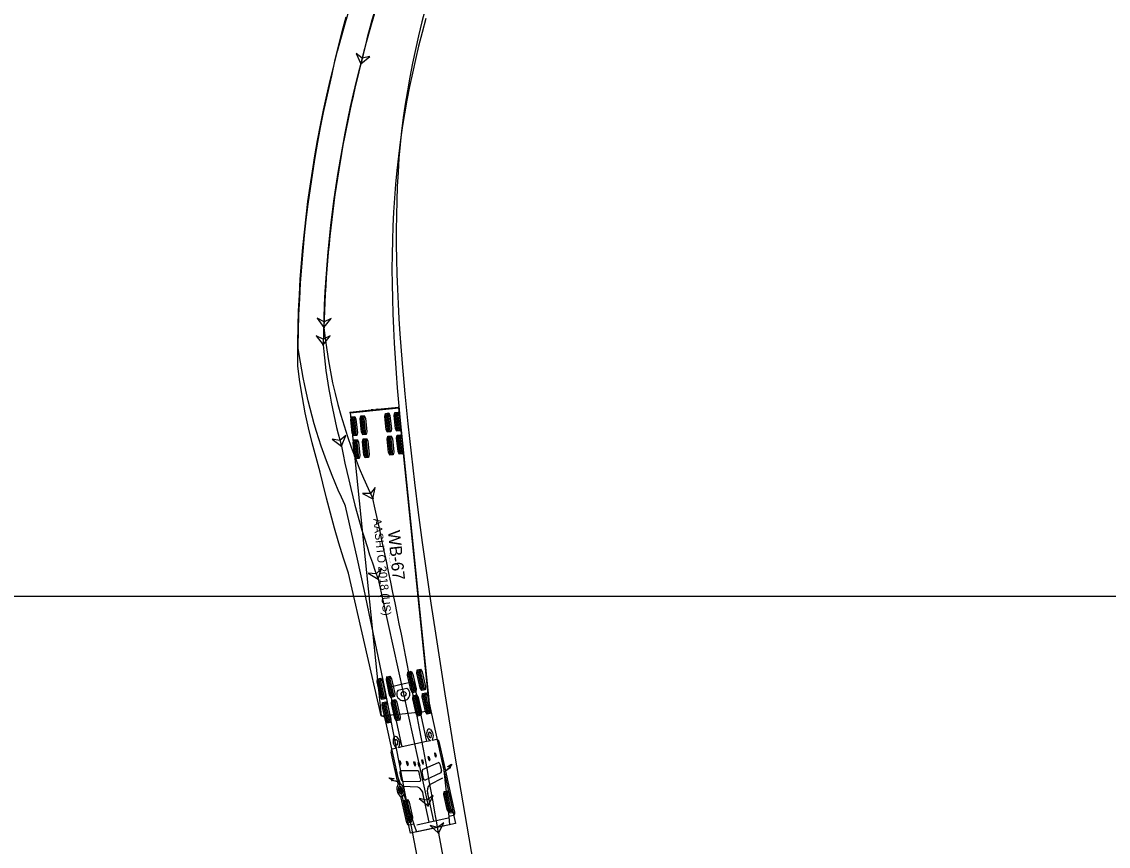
# Model space of a CAD drawing. Extents: x 973688 to 979179, y 703586 to 707602.
# Drawn here: x 978401 to 978589.5, y 703665.8 to 703808.9 of the extents above; entities that cross this region are included whole.
import ezdxf

# ---------------------------------------------------------------- set-up
doc = ezdxf.new("R2010")
doc.units = 0
for name, color, linetype in [('NO PLOT', 7, 'Continuous'), ('Radius Check', 7, 'Continuous'), ('T_Drafting', 7, 'Continuous')]:
    doc.layers.add(name, color=color, linetype=linetype)

msp = doc.modelspace()

# ---------------------------------------------------------------- linework, layer by layer
at = {"layer": 'NO PLOT'}
msp.add_lwpolyline([(978152.67, 704149.22), (978832.67, 704149.22), (978832.67, 703709.22), (978152.67, 703709.22)], close=True, dxfattribs=at)
at = {"layer": 'Radius Check'}
for p, q in [((978457.95, 703741.06), (978466.4, 703741.93)), ((978461.64, 703741.51), (978461.9, 703741.54)), ((978462.17, 703741.56), (978462.18, 703741.49)), ((978462.43, 703741.59), (978462.7, 703741.62)), ((978464.95, 703737.75), (978464.61, 703741.03)), ((978466.13, 703737.87), (978465.79, 703741.15)), ((978466.36, 703737.89), (978466.02, 703741.18)), ((978466.59, 703737.92), (978466.25, 703741.2)), ((978458.59, 703737.09), (978458.25, 703740.38)), ((978458.82, 703737.12), (978458.48, 703740.4)), ((978459.04, 703737.14), (978458.71, 703740.42)), ((978460.23, 703737.26), (978459.89, 703740.55)), ((978460.46, 703737.29), (978460.12, 703740.57)), ((978460.68, 703737.31), (978460.35, 703740.59)), ((978464.49, 703737.7), (978464.15, 703740.98)), ((978464.72, 703737.72), (978464.38, 703741.01)), ((978459, 703733.11), (978458.66, 703736.4)), ((978459.22, 703733.14), (978458.89, 703736.42)), ((978459.45, 703733.16), (978459.11, 703736.44)), ((978460.64, 703733.28), (978460.3, 703736.57)), ((978460.87, 703733.31), (978460.53, 703736.59)), ((978461.09, 703733.33), (978460.76, 703736.61)), ((978464.9, 703733.72), (978464.56, 703737.01)), ((978465.13, 703733.75), (978464.79, 703737.03)), ((978465.36, 703733.77), (978465.02, 703737.05)), ((978466.54, 703733.89), (978466.2, 703737.17)), ((978466.77, 703733.91), (978466.43, 703737.2)), ((978467, 703733.94), (978466.66, 703737.22)), ((978462.8, 703712.18), (978471.5, 703672.86)), ((978468.85, 703692.52), (978468.06, 703696.1)), ((978469.07, 703692.57), (978468.28, 703696.15)), ((978469.3, 703692.62), (978468.5, 703696.2)), ((978470.46, 703692.87), (978469.67, 703696.45)), ((978470.68, 703692.92), (978469.89, 703696.5)), ((978470.91, 703692.97), (978470.11, 703696.55)), ((978463.54, 703691.34), (978462.75, 703694.92)), ((978463.77, 703691.39), (978462.97, 703694.97)), ((978463.99, 703691.44), (978463.2, 703695.02)), ((978465.16, 703691.7), (978464.36, 703695.28)), ((978465.38, 703691.75), (978464.59, 703695.33)), ((978465.6, 703691.8), (978464.81, 703695.38)), ((978467.81, 703693.24), (978466.23, 703692.89)), ((978469.98, 703688.47), (978469.19, 703692.05)), ((978470.2, 703688.52), (978469.41, 703692.09)), ((978471.37, 703688.77), (978470.58, 703692.35)), ((978471.59, 703688.82), (978470.8, 703692.4)), ((978471.82, 703688.87), (978471.02, 703692.45)), ((978464.45, 703687.24), (978463.66, 703690.82)), ((978464.68, 703687.29), (978463.88, 703690.87)), ((978464.9, 703687.34), (978464.11, 703690.92)), ((978466.06, 703687.6), (978465.27, 703691.18)), ((978466.29, 703687.65), (978465.49, 703691.23)), ((978466.51, 703687.7), (978465.72, 703691.28)), ((978469.76, 703688.42), (978468.96, 703692)), ((978467.01, 703683.13), (978471.24, 703684.07)), ((978466.5, 703680.69), (978466.59, 703680.71)), ((978466.58, 703680.14), (978466.5, 703680.69)), ((978466.59, 703680.71), (978466.75, 703680.18)), ((978470.41, 703680.82), (978470.5, 703680.84)), ((978470.5, 703680.27), (978470.41, 703680.82)), ((978470.5, 703680.84), (978470.66, 703680.31)), ((978471.53, 703681.41), (978471.62, 703681.43)), ((978471.62, 703680.84), (978471.53, 703681.41)), ((978471.62, 703681.43), (978471.78, 703680.88)), ((978472.64, 703682.05), (978472.72, 703682.07)), ((978472.72, 703681.5), (978472.64, 703682.05)), ((978472.72, 703682.07), (978472.88, 703681.54)), ((978474.01, 703681.16), (978475.07, 703671.01)), ((978465.72, 703679.32), (978466.63, 703676.67)), ((978469.72, 703678.95), (978466.71, 703678.95)), ((978467.77, 703680.58), (978467.86, 703680.6)), ((978467.86, 703680.03), (978467.77, 703680.58)), ((978467.86, 703680.6), (978468.02, 703680.07)), ((978469.04, 703680.51), (978469.12, 703680.53)), ((978469.12, 703679.97), (978469.04, 703680.51)), ((978469.12, 703680.53), (978469.28, 703680)), ((978469.79, 703680.36), (978469.88, 703680.38)), ((978469.87, 703679.82), (978469.79, 703680.36)), ((978469.88, 703680.38), (978470.04, 703679.86)), ((978470.54, 703679.14), (978473.27, 703680.4)), ((978473.55, 703680.08), (978473.79, 703678.98)), ((978474.5, 703678.96), (978474.52, 703678.87)), ((978475.28, 703679.67), (978475.3, 703679.68)), ((978475.3, 703679.68), (978475.32, 703679.7)), ((978465.17, 703677.43), (978465.15, 703677.44)), ((978465.2, 703677.44), (978465.17, 703677.43)), ((978466.2, 703677.12), (978466.22, 703677.03)), ((978466.6, 703678.54), (978466.84, 703677.44)), ((978467.08, 703677.11), (978470.09, 703677.12)), ((978470.2, 703677.52), (978469.96, 703678.63)), ((978470.71, 703677.63), (978470.46, 703678.74)), ((978473.71, 703678.58), (978470.98, 703677.32)), ((978471.77, 703676.58), (978474.04, 703677.73)), ((978469.68, 703676.11), (978467.13, 703676.2)), ((978475.13, 703671.78), (978474.34, 703675.36)), ((978475.35, 703671.83), (978474.56, 703675.41)), ((978475.58, 703671.88), (978474.79, 703675.46)), ((978467.27, 703674.81), (978469.04, 703669.68)), ((978468.22, 703670.25), (978467.42, 703673.83)), ((978468.44, 703670.3), (978467.65, 703673.88)), ((978468.66, 703670.35), (978467.87, 703673.93)), ((978471.7, 703670.04), (978470.64, 703674.81)), ((978472.51, 703670.22), (978471.46, 703674.99)), ((978475.22, 703671.9), (978475.63, 703671.99)), ((978475.3, 703671.56), (978475.22, 703671.9)), ((978475.7, 703671.64), (978475.3, 703671.56)), ((978475.63, 703671.99), (978475.7, 703671.64)), ((978468.53, 703670.42), (978468.13, 703670.33)), ((978468.13, 703670.33), (978468.2, 703669.98)), ((978468.2, 703669.98), (978468.61, 703670.07)), ((978468.61, 703670.07), (978468.53, 703670.42)), ((978469.53, 703669.56), (978474.96, 703670.76))]:
    msp.add_line(p, q, dxfattribs=at)
for points in [[(978471.09, 703809.48), (978470.45, 703807.1), (978469.85, 703804.71), (978469.29, 703802.37), (978468.76, 703800.03), (978468.27, 703797.68), (978467.82, 703795.32), (978467.4, 703792.95), (978467.01, 703790.51), (978466.66, 703788.07), (978466.35, 703785.61), (978466.07, 703783.15), (978465.84, 703780.73), (978465.65, 703778.32), (978465.49, 703775.91), (978465.37, 703773.47), (978465.29, 703771.02), (978465.24, 703768.52), (978465.22, 703765.98), (978465.24, 703763.43), (978465.29, 703760.87), (978465.36, 703758.31), (978465.47, 703755.73), (978465.6, 703753.15), (978465.75, 703750.57), (978465.93, 703747.98), (978466.13, 703745.39), (978466.58, 703740.29), (978471.68, 703690.67), (978472.77, 703685.66), (978476.27, 703669.82), (978468.46, 703668.09), (978463.99, 703688.26), (978463.36, 703688.49), (978457.66, 703713.27), (978456.81, 703715.86), (978456, 703718.45), (978455.24, 703721.04), (978454.53, 703723.64), (978453.85, 703726.24), (978453.23, 703728.84), (978452.79, 703730.78), (978452.06, 703733.32), (978451.37, 703735.88), (978450.74, 703738.46), (978450.18, 703741.07), (978449.69, 703743.72), (978449.25, 703746.43), (978448.88, 703749.15), (978448.86, 703750.52), (978448.88, 703753.27), (978448.94, 703756.03), (978449.03, 703758.78), (978449.16, 703761.53), (978449.32, 703764.28), (978449.52, 703767.02), (978449.76, 703769.76), (978450.03, 703772.44), (978450.32, 703775.1), (978450.65, 703777.74), (978451.02, 703780.38), (978451.41, 703783.01), (978451.85, 703785.65), (978452.32, 703788.31), (978452.82, 703790.97), (978453.36, 703793.62), (978453.92, 703796.2), (978454.51, 703798.76), (978455.13, 703801.3), (978455.78, 703803.82), (978456.45, 703806.33), (978457.16, 703808.84), (978457.91, 703811.38)], [(978453.27, 703752.85), (978454.51, 703754.42), (978453.28, 703753.85), (978452.07, 703754.45), (978453.27, 703752.85)], [(978457.96, 703741.13), (978457.94, 703741.13), (978457.95, 703741.06), (978458.53, 703735.42), (978463.36, 703688.48), (978467.59, 703688.91), (978471.82, 703689.35), (978466.98, 703736.29), (978466.4, 703741.93), (978466.4, 703742), (978466.37, 703742)], [(978461.9, 703741.61), (978461.63, 703741.58), (978461.63, 703741.58), (978461.64, 703741.51), (978461.61, 703741.51), (978457.99, 703741.13), (978457.99, 703741.13)], [(978462.43, 703741.59), (978461.91, 703741.54)], [(978466.35, 703741.99), (978466.35, 703741.99), (978462.73, 703741.62), (978462.7, 703741.62), (978462.69, 703741.69), (978462.69, 703741.69), (978462.42, 703741.66)], [(978456.45, 703735.28), (978457.2, 703737.13), (978456.18, 703736.24), (978454.85, 703736.48), (978456.45, 703735.28)], [(978462.8, 703712.18), (978463.42, 703714.09), (978462.47, 703713.12), (978461.12, 703713.27), (978462.8, 703712.18)], [(978466.34, 703682.98), (978467.01, 703683.13), (978466.96, 703683.36), (978464.72, 703693.48), (978466.83, 703693.95), (978468.94, 703694.42), (978471.18, 703684.3), (978471.24, 703684.07), (978471.91, 703684.21)], [(978465.24, 703682.74), (978466.06, 703682.92)], [(978472.18, 703684.28), (978473.01, 703684.46)], [(978473.38, 703684.02), (978474.5, 703678.96), (978475.29, 703679.55), (978475.29, 703679.55), (978475.29, 703679.59), (978475.29, 703679.59), (978475.29, 703679.59), (978475.28, 703679.67), (978475.27, 703679.67), (978474.93, 703679.61), (978474.91, 703679.71), (978475.56, 703680.12), (978475.56, 703680.12), (978475.58, 703680), (978475.58, 703680), (978475.32, 703679.7), (978475.32, 703679.7), (978475.34, 703679.61)], [(978465.17, 703677.36), (978465.15, 703677.44), (978465.15, 703677.44), (978464.79, 703677.61), (978464.78, 703677.61), (978464.76, 703677.73), (978464.76, 703677.73), (978465.52, 703677.63), (978465.54, 703677.53), (978465.2, 703677.44), (978465.2, 703677.44), (978465.22, 703677.36), (978465.22, 703677.36), (978465.22, 703677.36), (978465.24, 703677.33), (978465.24, 703677.33), (978466.2, 703677.12), (978465.08, 703682.18)], [(978475.33, 703679.47), (978474.53, 703678.87), (978474.52, 703678.86), (978476.09, 703671.77)], [(978466.32, 703676.6), (978466.23, 703677.02), (978466.21, 703677.03), (978465.24, 703677.24)], [(978467.8, 703669.93), (978466.79, 703674.47)], [(978471.5, 703672.86), (978472.35, 703674.67), (978471.28, 703673.83), (978469.97, 703674.14), (978471.5, 703672.86)], [(978475.92, 703671.2), (978475.08, 703671.02), (978475.07, 703671.01), (978475.22, 703669.59), (978475.16, 703669.57), (978472.37, 703668.95), (978469.57, 703668.33), (978469.51, 703668.32), (978469.04, 703669.68), (978469.03, 703669.68), (978468.2, 703669.49)]]:
    msp.add_lwpolyline(points, dxfattribs=at)
for points in [[(978453.27, 703752.85), (978454.51, 703754.42), (978453.28, 703753.85), (978452.07, 703754.45)], [(978465, 703737.75), (978464.43, 703737.7), (978464.21, 703738.14), (978463.97, 703740.5), (978464.09, 703740.98), (978464.66, 703741.04), (978464.88, 703740.59), (978465.13, 703738.23)], [(978466.64, 703737.92), (978466.07, 703737.86), (978465.86, 703738.31), (978465.61, 703740.67), (978465.74, 703741.15), (978466.31, 703741.21), (978466.52, 703740.76), (978466.77, 703738.4)], [(978459.1, 703737.15), (978458.53, 703737.09), (978458.31, 703737.53), (978458.07, 703739.89), (978458.19, 703740.37), (978458.76, 703740.43), (978458.98, 703739.99), (978459.22, 703737.62)], [(978460.74, 703737.32), (978460.17, 703737.26), (978459.95, 703737.7), (978459.71, 703740.06), (978459.83, 703740.54), (978460.4, 703740.6), (978460.62, 703740.16), (978460.87, 703737.79)], [(978456.45, 703735.28), (978457.2, 703737.13), (978456.18, 703736.24), (978454.85, 703736.48)], [(978459.51, 703733.17), (978458.94, 703733.11), (978458.72, 703733.55), (978458.48, 703735.91), (978458.6, 703736.39), (978459.17, 703736.45), (978459.39, 703736.01), (978459.63, 703733.64)], [(978461.15, 703733.34), (978460.58, 703733.28), (978460.36, 703733.72), (978460.12, 703736.08), (978460.24, 703736.56), (978460.81, 703736.62), (978461.03, 703736.18), (978461.27, 703733.81)], [(978465.41, 703733.78), (978464.84, 703733.72), (978464.62, 703734.16), (978464.38, 703736.52), (978464.5, 703737), (978465.07, 703737.06), (978465.29, 703736.62), (978465.54, 703734.25)], [(978467.05, 703733.94), (978466.48, 703733.89), (978466.27, 703734.33), (978466.02, 703736.69), (978466.15, 703737.17), (978466.71, 703737.23), (978466.93, 703736.78), (978467.18, 703734.42)], [(978462.8, 703712.18), (978463.42, 703714.09), (978462.47, 703713.12), (978461.12, 703713.27)], [(978469.35, 703692.63), (978468.79, 703692.5), (978468.51, 703692.97), (978467.94, 703695.55), (978468, 703696.08), (978468.56, 703696.21), (978468.84, 703695.74), (978469.41, 703693.17)], [(978470.96, 703692.98), (978470.4, 703692.86), (978470.13, 703693.33), (978469.55, 703695.9), (978469.61, 703696.44), (978470.17, 703696.56), (978470.45, 703696.1), (978471.02, 703693.52)], [(978464.05, 703691.45), (978463.49, 703691.33), (978463.21, 703691.79), (978462.64, 703694.37), (978462.7, 703694.91), (978463.25, 703695.03), (978463.53, 703694.57), (978464.1, 703691.99)], [(978465.66, 703691.81), (978465.1, 703691.69), (978464.82, 703692.15), (978464.25, 703694.73), (978464.31, 703695.27), (978464.87, 703695.39), (978465.14, 703694.93), (978465.72, 703692.35)], [(978470.26, 703688.53), (978469.7, 703688.4), (978469.42, 703688.87), (978468.85, 703691.45), (978468.91, 703691.98), (978469.47, 703692.11), (978469.75, 703691.64), (978470.32, 703689.07)], [(978471.87, 703688.88), (978471.31, 703688.76), (978471.03, 703689.22), (978470.46, 703691.8), (978470.52, 703692.34), (978471.08, 703692.46), (978471.36, 703692), (978471.93, 703689.42)], [(978464.96, 703687.35), (978464.4, 703687.23), (978464.12, 703687.69), (978463.55, 703690.27), (978463.6, 703690.81), (978464.16, 703690.93), (978464.44, 703690.47), (978465.01, 703687.89)], [(978466.57, 703687.71), (978466.01, 703687.59), (978465.73, 703688.05), (978465.16, 703690.63), (978465.21, 703691.17), (978465.77, 703691.29), (978466.05, 703690.83), (978466.62, 703688.25)], [(978475.63, 703671.9), (978475.08, 703671.77), (978474.8, 703672.24), (978474.23, 703674.81), (978474.28, 703675.35), (978474.84, 703675.48), (978475.12, 703675.01), (978475.69, 703672.43)], [(978468.72, 703670.36), (978468.16, 703670.24), (978467.88, 703670.7), (978467.31, 703673.28), (978467.37, 703673.82), (978467.93, 703673.94), (978468.21, 703673.48), (978468.78, 703670.9)], [(978471.5, 703672.86), (978472.35, 703674.67), (978471.28, 703673.83), (978469.97, 703674.14)]]:
    msp.add_lwpolyline(points, close=True, dxfattribs=at)
for centre, radius in [((978453.27, 703752.85), 0.0417), ((978453.27, 703752.85), 0.0417), ((978457.97, 703741.17), 0.0266), ((978466.36, 703742.03), 0.0266), ((978456.45, 703735.28), 0.0417), ((978456.45, 703735.28), 0.0417), ((978462.8, 703712.18), 0.0417), ((978462.8, 703712.18), 0.0417), ((978467.24, 703692.28), 0.424), ((978471.5, 703672.86), 0.0417)]:
    msp.add_circle(centre, radius, dxfattribs=at)
for centre, radius, start, end in [((978659.2, 703750.34), 205.94, 158.7027, 179.3023), ((978552.51, 703761.72), 99.63, 185.1102, 195.3922), ((978457.76, 703743.14), 2.02, 275.8792, 276.5629), ((978461.9, 703741.57), 0.0354, 100.1707, 272.3562), ((978461.9, 703741.57), 0.0352, 276.8535, 95.8539), ((978462.43, 703741.63), 0.0352, 95.9044, 274.9048), ((978462.43, 703741.63), 0.0353, 279.2153, 97.565), ((978466.36, 703742.03), 0.0363, 294.9566, 256.1179), ((978612.85, 703765.9), 159.37, 191.0777, 199.6969), ((978467.19, 703692.28), 1.14, 147.4905, 57.4905), ((978466.83, 703684.13), 1.42, 157.4945, 194.5624), ((978465.84, 703684.55), 0.346, 62.0848, 159.0978), ((978465.38, 703683.9), 1.14, 15.2058, 56.7266), ((978472.38, 703685.45), 1.14, 148.2545, 189.7752), ((978472.99, 703685.45), 1.73, 186.3172, 211.1157), ((978471.69, 703685.84), 0.346, 45.8832, 142.8963), ((978472.15, 703684.9), 0.729, 208.299, 250.813), ((978471.92, 703685.37), 0.362, 136.7871, 185.8281), ((978472.29, 703685.3), 0.732, 177.6644, 223.8988), ((978471.77, 703685.48), 0.172, 42.7921, 129.9427), ((978471.89, 703684.9), 0.169, 220.9249, 321.0436), ((978471.43, 703685.13), 0.664, 7.3944, 45.6161), ((978470.98, 703685.05), 1.42, 10.4187, 47.4865), ((978471.58, 703685.08), 0.522, 327.4959, 14.66), ((978471.28, 703684.97), 1.14, 322.1205, 16.9118), ((978465.69, 703682.31), 0.619, 136.6508, 192.4926), ((978466.58, 703683.93), 1.14, 188.0693, 242.8606), ((978466.38, 703684.01), 0.664, 159.365, 197.5867), ((978466.26, 703683.9), 0.522, 190.321, 237.4852), ((978465.92, 703684.19), 0.172, 75.0383, 162.1889), ((978465.83, 703684.02), 0.362, 19.153, 68.194), ((978466.06, 703683.61), 0.169, 243.9375, 344.0562), ((978465.53, 703683.8), 0.732, 341.0823, 27.3167), ((978465.83, 703683.5), 0.729, 314.1681, 356.682), ((978464.84, 703683.65), 1.73, 353.8654, 18.6639), ((978472.78, 703683.88), 0.619, 12.4885, 68.3302), ((978471.8, 703680.86), 0.184, 179.4437, 251.3357), ((978471.64, 703680.81), 0.157, 306.0365, 33.1462), ((978472.9, 703681.5), 0.184, 179.4437, 251.3357), ((978472.75, 703681.45), 0.157, 306.0365, 33.1462), ((978466.9, 703678.67), 0.332, 125.1471, 203.5691), ((978466.74, 703680.12), 0.157, 171.8349, 258.9446), ((978466.58, 703680.1), 0.184, 313.6453, 25.5374), ((978468.01, 703680.01), 0.157, 171.8349, 258.9446), ((978467.85, 703679.99), 0.184, 313.6453, 25.5374), ((978469.27, 703679.95), 0.157, 171.8349, 258.9446), ((978469.11, 703679.92), 0.184, 313.6453, 25.5374), ((978469.57, 703678.59), 0.387, 4.9282, 68.1552), ((978470.03, 703679.8), 0.157, 171.8349, 258.9446), ((978469.91, 703679.77), 0.157, 306.0365, 33.1462), ((978470.83, 703678.87), 0.387, 136.8258, 200.0529), ((978470.68, 703680.27), 0.184, 179.4437, 251.3357), ((978470.53, 703680.22), 0.157, 306.0365, 33.1462), ((978473.21, 703680.07), 0.332, 1.4119, 79.8339), ((978473.43, 703678.84), 0.387, 316.8234, 20.0553), ((978475.33, 703679.52), 0.0522, 268.7533, 13.6079), ((978475.27, 703679.53), 0.108, 3.3317, 49.5142), ((978465.27, 703677.31), 0.108, 155.4669, 201.6494), ((978465.22, 703677.28), 0.0522, 191.3731, 296.2277), ((978467.23, 703677.47), 0.387, 184.9257, 248.1577), ((978469.94, 703677.38), 0.296, 299.2093, 29.507), ((978471, 703677.61), 0.296, 175.4741, 265.7718), ((978467.6, 703675.77), 1.53, 146.9833, 237.9923), ((978467.34, 703675.74), 1.03, 165.3142, 193.7007), ((978466.54, 703676.33), 0.347, 74.8177, 129.6283), ((978466.98, 703675.53), 0.634, 183.0744, 259.0761), ((978466.66, 703675.94), 0.317, 108.3407, 169.9331), ((978467.1, 703675.66), 0.589, 165.2461, 208.2288), ((978466.69, 703675.76), 0.17, 110.1596, 164.2239), ((978466.54, 703675.81), 0.44, 24.2848, 88.0976), ((978466.79, 703675.45), 0.223, 199.7254, 269.3279), ((978466.15, 703675.64), 1.14, 11.1951, 64.9976), ((978466.61, 703675.66), 0.263, 11.4254, 85.3274), ((978466.74, 703675.38), 0.158, 287.4618, 348.9745), ((978466.73, 703675.25), 0.366, 290.5429, 3.0239), ((978466.33, 703675.49), 0.575, 345.5656, 22.136), ((978465.91, 703675.4), 1.19, 353.6217, 29.5111), ((978465.65, 703675.32), 1.7, 342.4112, 18.3193), ((978469.13, 703674.7), 1.52, 4.0706, 68.498), ((978472.87, 703675.53), 1.52, 136.4831, 200.9105), ((978466.86, 703674.9), 0.425, 260.5535, 347.0898), ((978475.64, 703671.6), 0.486, 304.9535, 20.9046), ((978468.28, 703669.97), 0.486, 184.0765, 260.0276)]:
    msp.add_arc(centre, radius, start, end, dxfattribs=at)
for centre, major_axis, start_param, end_param in [((978475.33, 703679.54), (0.0169, -0.0764), 2.615166, 3.884468), ((978475.33, 703679.54), (-0.0169, 0.0764), 1.301202, 2.571945), ((978465.2, 703677.3), (0.0169, -0.0764), 2.398717, 3.668019), ((978465.2, 703677.3), (0.0169, -0.0764), 0.569648, 1.840391)]:
    msp.add_ellipse(centre, major_axis=major_axis, ratio=0.544872, start_param=start_param, end_param=end_param, dxfattribs=at)
at = {"layer": 'T_Drafting'}
msp.add_line((978473.31, 703668.11), (978487.91, 703590.57), dxfattribs=at)
for points in [[(978471.05, 703811.31), (978470.43, 703808.91), (978469.84, 703806.51), (978469.29, 703804.12), (978468.78, 703801.73), (978468.32, 703799.35), (978467.89, 703796.98), (978467.51, 703794.63), (978467.18, 703792.32), (978466.89, 703789.99), (978466.65, 703787.64), (978466.44, 703785.27), (978466.27, 703782.84), (978466.14, 703780.36), (978466.04, 703777.85), (978465.99, 703775.34), (978465.96, 703772.8), (978465.97, 703770.26), (978466, 703767.7), (978466.07, 703765.14), (978466.16, 703762.56), (978466.28, 703759.98), (978466.43, 703757.4), (978466.59, 703754.8), (978466.98, 703749.61), (978467.44, 703744.39), (978467.97, 703739.18), (978468.53, 703734.08), (978469.14, 703728.97), (978469.79, 703723.78), (978470.49, 703718.54), (978471.22, 703713.29), (978471.98, 703708.05), (978472.76, 703702.8), (978474.39, 703692.31), (978476.09, 703681.82), (978477.85, 703671.33), (978479.65, 703660.88)], [(978472.71, 703647.82), (978466.76, 703678.93), (978464.72, 703689.42), (978463.67, 703694.66), (978462.6, 703699.91), (978461.5, 703705.15), (978460.37, 703710.4), (978459.22, 703715.65), (978457.14, 703724.85), (978457.02, 703725.17), (978456.44, 703726.42), (978455.88, 703727.67), (978455.34, 703728.93), (978454.83, 703730.19), (978453.85, 703732.73), (978452.95, 703735.28), (978452.12, 703737.85), (978451.73, 703739.17), (978451.36, 703740.49), (978451.01, 703741.82), (978450.68, 703743.15), (978450.37, 703744.49), (978450.08, 703745.83), (978449.81, 703747.18), (978449.56, 703748.53), (978449.33, 703749.88), (978448.97, 703752.25), (978448.96, 703752.59), (978449.01, 703755.34), (978449.09, 703758.1), (978449.21, 703760.85), (978449.37, 703763.6), (978449.56, 703766.35), (978449.79, 703769.1), (978450.06, 703771.84), (978450.36, 703774.58), (978450.69, 703777.31), (978451.06, 703780.03), (978451.47, 703782.74), (978451.9, 703785.41), (978452.36, 703788.02), (978452.85, 703790.61), (978453.36, 703793.18), (978453.91, 703795.73), (978454.78, 703799.54), (978455.33, 703802.12), (978455.93, 703804.69), (978456.57, 703807.26), (978457.25, 703809.82)], [(978459.83, 703801.63), (978461.37, 703802.91), (978460.05, 703802.6), (978458.99, 703803.45), (978459.83, 703801.63)], [(978453.41, 703755.87), (978454.67, 703757.43), (978453.44, 703756.87), (978452.24, 703757.49), (978453.41, 703755.87)], [(978461.92, 703726.17), (978462.31, 703728.13), (978461.48, 703727.07), (978460.13, 703727.06), (978461.92, 703726.17)], [(978473.31, 703668.11), (978474.23, 703669.89), (978473.14, 703669.1), (978471.84, 703669.47), (978473.31, 703668.11)]]:
    msp.add_lwpolyline(points, dxfattribs=at)
for points in [[(978459.83, 703801.63), (978461.37, 703802.91), (978460.05, 703802.6), (978458.99, 703803.45)], [(978453.41, 703755.87), (978454.67, 703757.43), (978453.44, 703756.87), (978452.24, 703757.49)], [(978461.92, 703726.17), (978462.31, 703728.13), (978461.48, 703727.07), (978460.13, 703727.06)], [(978473.31, 703668.11), (978474.23, 703669.89), (978473.14, 703669.1), (978471.84, 703669.47)]]:
    msp.add_lwpolyline(points, close=True, dxfattribs=at)
for centre in [(978459.83, 703801.63), (978459.83, 703801.63), (978453.41, 703755.87), (978453.41, 703755.87), (978461.92, 703726.17), (978461.92, 703726.17), (978473.31, 703668.11), (978473.31, 703668.11)]:
    msp.add_circle(centre, 0.0417, dxfattribs=at)
for centre, radius, start, end in [((978616.18, 703766.2), 160.31, 154.4507, 167.2335), ((978660.24, 703750.19), 206.91, 165.6047, 178.4259), ((978540.63, 703764.78), 87.67, 185.8285, 206.1262), ((977147.3, 703438.14), 1345.8, 9.83916, 12.35819)]:
    msp.add_arc(centre, radius, start, end, dxfattribs=at)

# ---------------------------------------------------------------- texts
at = {"layer": 'Radius Check'}
for s, height, p in [('AASHTO 2018 (US)', 1.4167, (978461.97, 703722.68)), ('WB-67', 2.125, (978464.5, 703720.57)), ('(c) 2021 Transoft Solutions, Inc. All rights reserved.', 0.085, (978464.66, 703716.99))]:
    msp.add_text(s, height=height, rotation=275.8792, dxfattribs=at).set_placement(p)

doc.saveas('drawing.dxf')
